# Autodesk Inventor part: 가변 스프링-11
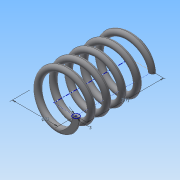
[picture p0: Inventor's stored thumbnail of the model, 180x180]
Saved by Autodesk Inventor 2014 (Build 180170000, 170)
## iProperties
Created: 2015-09
Part Number: 가변 스프링-11
Material: 강철, 탄소
Document SubType Name: Modeling
Designer: study
Density: 7.87 g/cm^3
Appearance: 반연마
Mass: 18.8856 g
Surface Area: 32.5491 cm^2
Volume: 2.3997 cm^3
Author: study
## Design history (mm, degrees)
sketch "스케치1"
  geometry: L1 (0, 0)-(11, 0); L2 (11, 0)-(11, 36.411); L3 (11, 36.411)-(0, 36.411); L4 (0, 36.411)-(0, 0); C1 r 1.5 at (11, 0)
  constraints: 8 end point, 2 parallel, 1 centre point, 1 coincident, 1 horizontal, 1 perpendicular
  dimensions: "d0" = 36.4112 distance of L1.end L2.end (derived); "d1" = 22 diameter of L1.end L4; "d2" = 3 diameter of C1
feature "코일1" sketch "스케치1" pitch "d3" = 10; turns "d5" = 5; dims "d4" = 36.4112 (= d0), "d6" = 0, angle "d7" = 90 deg, angle "d8" = 90 deg, "d9" = 0, "d10" = 0
node "작업 평면1"
sketch "스케치2"
  geometry: L1 (-12.5, 0)-(-9.5, 0) reference; 1 further point
  constraints: 1 horizontal alignment
extrude "돌출1" cut sketch "스케치2" stored distance "d12" = 10; taper "d13" = 0 deg
node "작업 평면2"
sketch "스케치3"
  geometry: L1 (-9.5, 0)-(-12.5, 0) reference; 1 further point
  constraints: 1 horizontal alignment
extrude "돌출2" cut sketch "스케치3" stored distance "d15" = 10; taper "d16" = 0 deg
node "솔리드1"
node "절단 모서리 투영1"
node "절단 모서리 투영2"
other parameters: "d11" = 0, "d14" = 36.4112 (= d0)
